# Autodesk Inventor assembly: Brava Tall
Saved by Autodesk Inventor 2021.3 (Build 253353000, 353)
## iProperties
Created: 2022-09
Part Number: Brava Tall
Document SubType Name: Assembly
Designer: Administrator
Title: Brava Tall v7
Author: Administrator
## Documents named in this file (3)
- c:\worker\convert-fusion-r05\tmp\job-1\51\output\files\468e93a4-682b-43d8-a1fc-56125033c8de\2bd8427d-c528-4fa1-8ba6-018dbcf7f206.iam
- c:\worker\convert-fusion-r05\tmp\job-1\51\output\files\468e93a4-682b-43d8-a1fc-56125033c8de\Brava Tall.ipt
- c:\worker\convert-fusion-r05\tmp\job-1\51\output\files\468e93a4-682b-43d8-a1fc-56125033c8de\Part4.ipt
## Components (2 placed, 2 different names)
1. Brava Tall:1
2. Part4
